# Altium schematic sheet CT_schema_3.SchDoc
size 362 x 192 mm
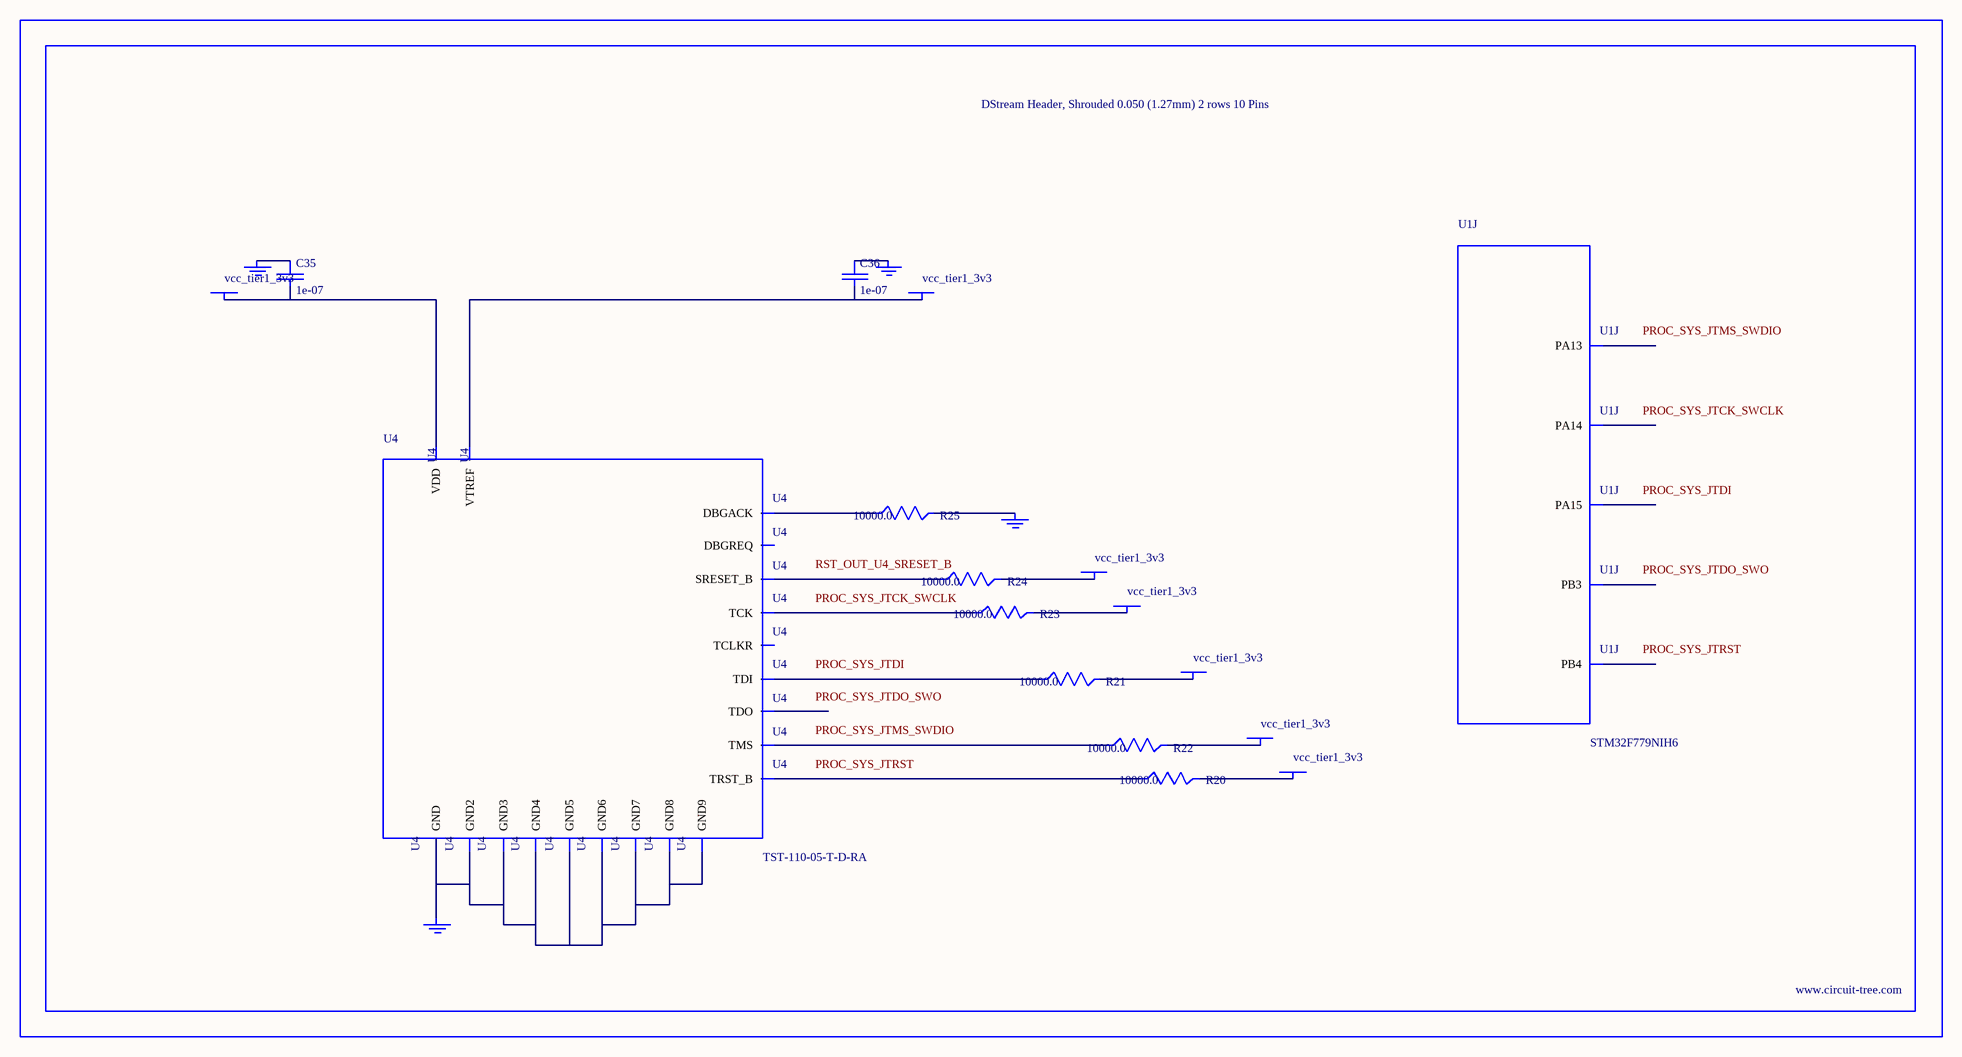
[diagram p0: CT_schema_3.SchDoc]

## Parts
BORDER2  (no value)
C35  1e-07  [C0402]
C36  1e-07  [C0402]
GND_INSTANCE_2_0  (no value)
GND_INSTANCE_2_1  (no value)
GND_INSTANCE_2_2  (no value)
GND_INSTANCE_2_3  (no value)
POWER_INSTANCE_2_0  vcc_tier1_3v3
POWER_INSTANCE_2_1  vcc_tier1_3v3
POWER_INSTANCE_2_2  vcc_tier1_3v3
POWER_INSTANCE_2_3  vcc_tier1_3v3
POWER_INSTANCE_2_4  vcc_tier1_3v3
POWER_INSTANCE_2_5  vcc_tier1_3v3
POWER_INSTANCE_2_6  vcc_tier1_3v3
R20  10000.0  [R0603]
R21  10000.0  [R0603]
R22  10000.0  [R0603]
R23  10000.0  [R0603]
R24  10000.0  [R0603]
R25  10000.0  [R0603]
U1  STM32F779NIH6  [TFBGA216]  (part J of 16)
U4  TST-110-05-T-D-RA  [TST-110-05-T-D-RA]

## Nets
NetC35_1: C35.1 GND_INSTANCE_2_1.0(GND)
NetC35_2: C35.2 POWER_INSTANCE_2_1.0(PWR) U4.2(VDD)
NetC36_1: C36.1 GND_INSTANCE_2_0.0(GND)
NetC36_2: C36.2 POWER_INSTANCE_2_0.0(PWR) U4.1(VTREF)
NetGND_INSTANCE_2_2_0: GND_INSTANCE_2_2.0(GND) R25.2
NetGND_INSTANCE_2_3_0: GND_INSTANCE_2_3.0(GND) U4.4(GND) U4.6(GND2) U4.8(GND3) U4.10(GND4) U4.12(GND5) U4.14(GND6) U4.16(GND7) U4.18(GND8) U4.20(GND9)
NetPOWER_INSTANCE_2_2_0: POWER_INSTANCE_2_2.0(PWR) R20.2
NetPOWER_INSTANCE_2_3_0: POWER_INSTANCE_2_3.0(PWR) R21.2
NetPOWER_INSTANCE_2_4_0: POWER_INSTANCE_2_4.0(PWR) R22.2
NetPOWER_INSTANCE_2_5_0: POWER_INSTANCE_2_5.0(PWR) R23.2
NetPOWER_INSTANCE_2_6_0: POWER_INSTANCE_2_6.0(PWR) R24.2
NetR20_1: R20.1 U4.3(TRST_B)
NetR21_1: R21.1 U4.5(TDI)
NetR22_1: R22.1 U4.7(TMS)
NetR23_1: R23.1 U4.9(TCK)
NetR24_1: R24.1 U4.15(SRESET_B)
NetR25_1: R25.1 U4.19(DBGACK)

Not connected (* = marked no-connect by the designer): U1 A9(PB4) A10(PB3) A13(PA15) A14(PA14) A15(PA13); U4 11(TCLKR) 13(TDO) 17(DBGREQ)

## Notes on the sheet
- Labels drawn without touching a wire or pin: PROC_SYS_JTCK_SWCLK, PROC_SYS_JTDI, PROC_SYS_JTDO_SWO, PROC_SYS_JTMS_SWDIO, PROC_SYS_JTRST, RST_OUT_U4_SRESET_B

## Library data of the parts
BORDER2 = BORDER_PAGE2
C35 C36 = C0402C104K3RACTU
GND_INSTANCE_2_0-GND_INSTANCE_2_3 = GND
POWER_INSTANCE_2_0-POWER_INSTANCE_2_6 = PWR
R20-R25 = RC0603JR-0710KL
